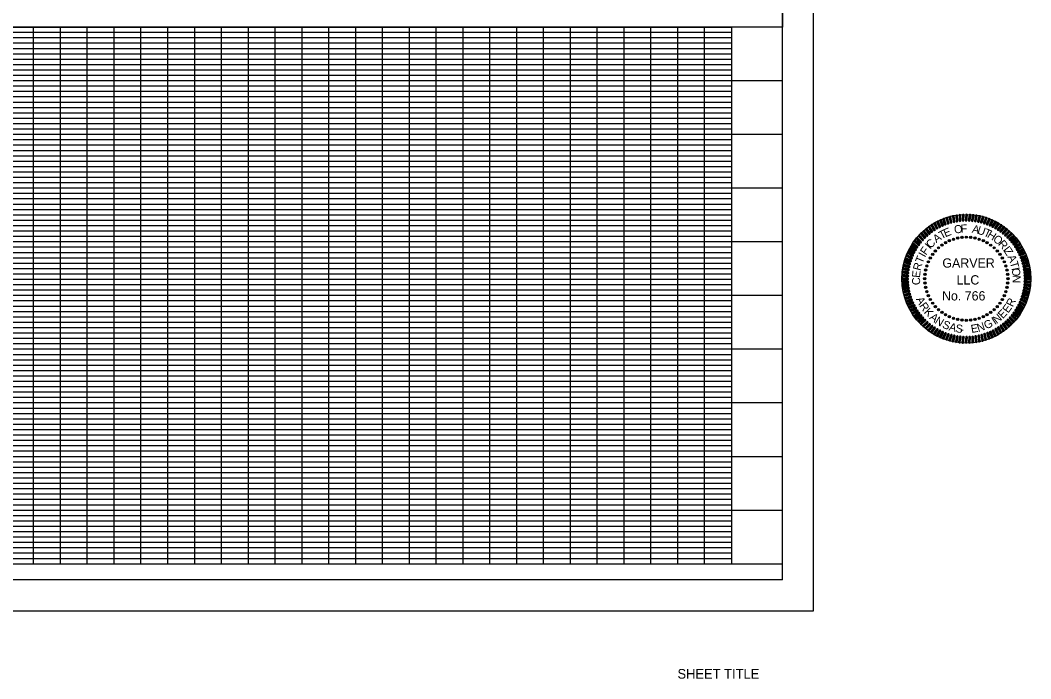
# Model space of a CAD drawing. Extents: x 0 to 762217, y -63 to 1662473.
# Drawn here: x 961 to 1902, y -63 to 550 of the extents above; entities that cross this region are included whole.
import ezdxf

# ---------------------------------------------------------------- set-up
doc = ezdxf.new("R2010")
doc.units = 0
for name, color, linetype in [('G-ANNO-TEXT', 7, 'Continuous'), ('G-Border-Paper', 7, 'Continuous'), ('G-Border-Sheet', 7, 'Continuous'), ('G-Grid-Border', 7, 'Continuous'), ('G-Grid-Major', 7, 'Continuous'), ('G-Grid-Minor', 7, 'Continuous'), ('G-No Plot-Border', 7, 'Continuous'), ('G-No Plot-Border-2', 7, 'Continuous'), ('G-No Plot-Stamp', 7, 'Continuous')]:
    doc.layers.add(name, color=color, linetype=linetype)

# ---------------------------------------------------------------- blocks, each defined once
blk = doc.blocks.new('SEALDO')
at = {"layer": 'G-ANNO-TEXT'}
for radius in [0.0396, 0.0305, 0.0213, 0.0122, 0.00305]:
    blk.add_circle((1.403, -0.456), radius, dxfattribs=at)
blk = doc.blocks.new('SEALRI')
at = {"layer": 'G-ANNO-TEXT'}
for p, q in [((-0.023, 2.258), (-0.038, 2.081)), ((-0.008, 2.281), (-0.028, 2.056)), ((0.004, 2.286), (-0.016, 2.049)), ((0.016, 2.285), (-0.004, 2.048)), ((0.028, 2.278), (0.008, 2.052)), ((0.023, 2.076), (0.038, 2.253))]:
    blk.add_line(p, q, dxfattribs=at)
for centre, start, end in [((0.008, 2.256), 355, 175), ((-0.008, 2.078), 175, 355)]:
    blk.add_arc(centre, 0.0305, start, end, dxfattribs=at)

msp = doc.modelspace()

# ---------------------------------------------------------------- linework, layer by layer
at = {"layer": 'G-Border-Paper'}
msp.add_lwpolyline([(1700.05, 1100), (0.05, 1100), (0.05, 0), (1700.05, 0)], close=True, dxfattribs=at)
at = {"layer": 'G-Border-Sheet'}
for q in [(1671.21, 1071.16), (75.85, 28.84)]:
    msp.add_line((1671.21, 28.84), q, dxfattribs=at)
at = {"layer": 'G-Grid-Border'}
for p, q in [((1671.21, 543.54), (75.85, 543.54)), ((1671.21, 43.54), (75.85, 43.54))]:
    msp.add_line(p, q, dxfattribs=at)
msp.add_lwpolyline([(123.53, 543.54), (1623.53, 543.54), (1623.53, 43.54), (123.53, 43.54)], close=True, dxfattribs=at)
at = {"layer": 'G-Grid-Major'}
for p, q in [((973.53, 43.54), (973.53, 543.54)), ((1023.53, 43.54), (1023.53, 543.54)), ((1073.53, 43.54), (1073.53, 543.54)), ((1123.53, 43.54), (1123.53, 543.54)), ((1173.53, 43.54), (1173.53, 543.54)), ((1223.53, 43.54), (1223.53, 543.54)), ((1273.53, 43.54), (1273.53, 543.54)), ((1323.53, 43.54), (1323.53, 543.54)), ((1373.53, 43.54), (1373.53, 543.54)), ((1423.53, 43.54), (1423.53, 543.54)), ((1473.53, 43.54), (1473.53, 543.54)), ((1523.53, 43.54), (1523.53, 543.54)), ((1573.53, 43.54), (1573.53, 543.54)), ((1671.21, 493.54), (75.85, 493.54)), ((1671.21, 443.54), (75.85, 443.54)), ((1671.21, 393.54), (75.85, 393.54)), ((1671.21, 343.54), (75.85, 343.54)), ((1671.21, 293.54), (75.85, 293.54)), ((1671.21, 243.54), (75.85, 243.54)), ((1671.21, 193.54), (75.85, 193.54)), ((1671.21, 143.54), (75.85, 143.54)), ((1671.21, 93.54), (75.85, 93.54))]:
    msp.add_line(p, q, dxfattribs=at)
msp.add_lwpolyline([(123.53, 543.54), (1623.53, 543.54), (1623.53, 43.54), (123.53, 43.54)], close=True, dxfattribs=at)
at = {"layer": 'G-Grid-Minor'}
for p, q in [((1623.53, 538.54), (123.53, 538.54)), ((998.53, 43.54), (998.53, 543.54)), ((1048.53, 43.54), (1048.53, 543.54)), ((1098.53, 43.54), (1098.53, 543.54)), ((1148.53, 43.54), (1148.53, 543.54)), ((1198.53, 43.54), (1198.53, 543.54)), ((1248.53, 43.54), (1248.53, 543.54)), ((1298.53, 43.54), (1298.53, 543.54)), ((1348.53, 43.54), (1348.53, 543.54)), ((1398.53, 43.54), (1398.53, 543.54)), ((1448.53, 43.54), (1448.53, 543.54)), ((1498.53, 43.54), (1498.53, 543.54)), ((1548.53, 43.54), (1548.53, 543.54)), ((1598.53, 43.54), (1598.53, 543.54)), ((1623.53, 533.54), (123.53, 533.54)), ((1623.53, 528.54), (123.53, 528.54)), ((1623.53, 523.54), (123.53, 523.54)), ((1623.53, 518.54), (123.53, 518.54)), ((1623.53, 513.54), (123.53, 513.54)), ((1623.53, 508.54), (123.53, 508.54)), ((1623.53, 503.54), (123.53, 503.54)), ((1623.53, 498.54), (123.53, 498.54)), ((1623.53, 488.54), (123.53, 488.54)), ((1623.53, 483.54), (123.53, 483.54)), ((1623.53, 478.54), (123.53, 478.54)), ((1623.53, 473.54), (123.53, 473.54)), ((1623.53, 468.54), (123.53, 468.54)), ((1623.53, 463.54), (123.53, 463.54)), ((1623.53, 458.54), (123.53, 458.54)), ((1623.53, 453.54), (123.53, 453.54)), ((1623.53, 448.54), (123.53, 448.54)), ((1623.53, 438.54), (123.53, 438.54)), ((1623.53, 433.54), (123.53, 433.54)), ((1623.53, 428.54), (123.53, 428.54)), ((1623.53, 423.54), (123.53, 423.54)), ((1623.53, 418.54), (123.53, 418.54)), ((1623.53, 413.54), (123.53, 413.54)), ((1623.53, 408.54), (123.53, 408.54)), ((1623.53, 403.54), (123.53, 403.54)), ((1623.53, 398.54), (123.53, 398.54)), ((1623.53, 388.54), (123.53, 388.54)), ((1623.53, 383.54), (123.53, 383.54)), ((1623.53, 378.54), (123.53, 378.54)), ((1623.53, 373.54), (123.53, 373.54)), ((1623.53, 368.54), (123.53, 368.54)), ((1623.53, 363.54), (123.53, 363.54)), ((1623.53, 358.54), (123.53, 358.54)), ((1623.53, 353.54), (123.53, 353.54)), ((1623.53, 348.54), (123.53, 348.54)), ((1623.53, 338.54), (123.53, 338.54)), ((1623.53, 333.54), (123.53, 333.54)), ((1623.53, 328.54), (123.53, 328.54)), ((1623.53, 323.54), (123.53, 323.54)), ((1623.53, 318.54), (123.53, 318.54)), ((1623.53, 313.54), (123.53, 313.54)), ((1623.53, 308.54), (123.53, 308.54)), ((1623.53, 303.54), (123.53, 303.54)), ((1623.53, 298.54), (123.53, 298.54)), ((1623.53, 288.54), (123.53, 288.54)), ((1623.53, 283.54), (123.53, 283.54)), ((1623.53, 278.54), (123.53, 278.54)), ((1623.53, 273.54), (123.53, 273.54)), ((1623.53, 268.54), (123.53, 268.54)), ((1623.53, 263.54), (123.53, 263.54)), ((1623.53, 258.54), (123.53, 258.54)), ((1623.53, 253.54), (123.53, 253.54)), ((1623.53, 248.54), (123.53, 248.54)), ((1623.53, 238.54), (123.53, 238.54)), ((1623.53, 233.54), (123.53, 233.54)), ((1623.53, 228.54), (123.53, 228.54)), ((1623.53, 223.54), (123.53, 223.54)), ((1623.53, 218.54), (123.53, 218.54)), ((1623.53, 213.54), (123.53, 213.54)), ((1623.53, 208.54), (123.53, 208.54)), ((1623.53, 203.54), (123.53, 203.54)), ((1623.53, 198.54), (123.53, 198.54)), ((1623.53, 188.54), (123.53, 188.54)), ((1623.53, 183.54), (123.53, 183.54)), ((1623.53, 178.54), (123.53, 178.54)), ((1623.53, 173.54), (123.53, 173.54)), ((1623.53, 168.54), (123.53, 168.54)), ((1623.53, 163.54), (123.53, 163.54)), ((1623.53, 158.54), (123.53, 158.54)), ((1623.53, 153.54), (123.53, 153.54)), ((1623.53, 148.54), (123.53, 148.54)), ((1623.53, 138.54), (123.53, 138.54)), ((1623.53, 133.54), (123.53, 133.54)), ((1623.53, 128.54), (123.53, 128.54)), ((1623.53, 123.54), (123.53, 123.54)), ((1623.53, 118.54), (123.53, 118.54)), ((1623.53, 113.54), (123.53, 113.54)), ((1623.53, 108.54), (123.53, 108.54)), ((1623.53, 103.54), (123.53, 103.54)), ((1623.53, 98.54), (123.53, 98.54)), ((1623.53, 88.54), (123.53, 88.54)), ((1623.53, 83.54), (123.53, 83.54)), ((1623.53, 78.54), (123.53, 78.54)), ((1623.53, 73.54), (123.53, 73.54)), ((1623.53, 68.54), (123.53, 68.54)), ((1623.53, 63.54), (123.53, 63.54)), ((1623.53, 58.54), (123.53, 58.54)), ((1623.53, 53.54), (123.53, 53.54)), ((1623.53, 48.54), (123.53, 48.54))]:
    msp.add_line(p, q, dxfattribs=at)
at = {"layer": 'G-No Plot-Border'}
msp.add_lwpolyline([(75.85, 543.54), (75.85, 1071.16), (1273.86, 1071.16), (1273.86, 1021.61), (1472.11, 1021.61), (1472.11, 1006.11), (1543.71, 1006.11), (1543.71, 858.61), (1671.21, 858.61), (1671.21, 543.54)], close=True, dxfattribs=at)
at = {"layer": 'G-No Plot-Border-2'}
msp.add_lwpolyline([(75.85, 1071.16), (1147.43, 1071.16), (1147.43, 923.66), (1273.86, 923.66), (1273.86, 1021.61), (1472.11, 1021.61), (1472.11, 1006.11), (1671.21, 1006.11), (1671.21, 543.54), (75.85, 543.54)], close=True, dxfattribs=at)
at = {"layer": 'G-No Plot-Stamp'}
msp.add_circle((1842.27, 309.25), 60, dxfattribs=at)
msp.add_circle((1842.27, 309.25), 60, dxfattribs=at)

# ---------------------------------------------------------------- block references
at = {"layer": 'G-ANNO-TEXT'}
for name, xscale, yscale, rotation in [('SEALRI', 26.24620298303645, 26.24620298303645, 15.000000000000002), ('SEALRI', 26.246202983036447, 26.246202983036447, 12.000000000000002), ('SEALRI', 26.246202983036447, 26.246202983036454, 9), ('SEALRI', 26.246202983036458, 26.246202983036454, 6), ('SEALRI', 26.246202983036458, 26.246202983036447, 3.0000000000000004), ('SEALRI', 26.246202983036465, 26.246202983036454, -2.9999999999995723), ('SEALRI', 26.24620298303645, 26.246202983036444, -5.9999999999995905), ('SEALRI', 26.246202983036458, 26.24620298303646, -8.999999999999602), ('SEALRI', 26.246202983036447, 26.246202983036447, -11.999999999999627), ('SEALRI', 26.24620298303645, 26.246202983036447, -14.999999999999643), ('SEALRI', 26.24620298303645, 26.246202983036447, 36), ('SEALRI', 26.24620298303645, 26.246202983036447, 33), ('SEALRI', 26.24620298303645, 26.246202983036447, 30.00000000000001), ('SEALRI', 26.246202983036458, 26.246202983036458, 26.999999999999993), ('SEALRI', 26.246202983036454, 26.24620298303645, 23.99999999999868), ('SEALRI', 26.246202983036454, 26.24620298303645, 20.99999999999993), ('SEALRI', 26.246202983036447, 26.24620298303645, 18), ('SEALRI', 26.24620298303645, 26.24620298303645, -17.999999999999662), ('SEALRI', 26.24620298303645, 26.246202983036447, -20.999999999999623), ('SEALRI', 26.246202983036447, 26.24620298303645, -23.99999999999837), ('SEALRI', 26.246202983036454, 26.24620298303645, -26.999999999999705), ('SEALRI', 26.24620298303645, 26.246202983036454, -29.99999999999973), ('SEALRI', 26.24620298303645, 26.246202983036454, -32.999999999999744), ('SEALRI', 26.24620298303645, 26.246202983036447, -35.999999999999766), ('SEALRI', 26.246202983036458, 26.246202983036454, 47.99999999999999), ('SEALRI', 26.24620298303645, 26.246202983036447, 44.999999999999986), ('SEALRI', 26.246202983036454, 26.24620298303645, 41.999999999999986), ('SEALRI', 26.246202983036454, 26.24620298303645, 38.999999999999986), ('SEALDO', 26.246202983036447, 26.24620298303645, 119.99999999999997), ('SEALDO', 26.24620298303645, 26.246202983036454, 113.99999999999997), ('SEALDO', 26.24620298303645, 26.246202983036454, 107.99999999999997), ('SEALDO', 26.24620298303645, 26.246202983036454, 101.99999999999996), ('SEALRI', 26.24620298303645, 26.24620298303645, -38.99999999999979), ('SEALRI', 26.24620298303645, 26.24620298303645, -41.99999999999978), ('SEALRI', 26.246202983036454, 26.24620298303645, -44.99999999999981), ('SEALRI', 26.246202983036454, 26.24620298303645, -47.99999999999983), ('SEALRI', 26.246202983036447, 26.24620298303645, 59.999999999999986), ('SEALRI', 26.246202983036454, 26.246202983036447, 56.99999999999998), ('SEALRI', 26.24620298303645, 26.246202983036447, 54), ('SEALRI', 26.246202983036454, 26.24620298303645, 50.99999999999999), ('SEALDO', 26.246202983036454, 26.24620298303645, 150), ('SEALDO', 26.246202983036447, 26.24620298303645, 144), ('SEALDO', 26.24620298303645, 26.246202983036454, 138), ('SEALDO', 26.246202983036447, 26.246202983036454, 131.99999999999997), ('SEALDO', 26.246202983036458, 26.246202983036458, 125.99999999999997), ('SEALDO', 26.246202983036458, 26.246202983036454, 95.99999999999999), ('SEALDO', 26.246202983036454, 26.24620298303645, 90), ('SEALDO', 26.246202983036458, 26.246202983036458, 83.99999999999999), ('SEALDO', 26.246202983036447, 26.24620298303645, 77.99999999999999), ('SEALDO', 26.246202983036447, 26.24620298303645, 72), ('SEALDO', 26.246202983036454, 26.24620298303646, 66.00000000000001), ('SEALRI', 26.246202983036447, 26.24620298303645, -50.99999999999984), ('SEALRI', 26.24620298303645, 26.24620298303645, -53.99999999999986), ('SEALRI', 26.246202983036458, 26.246202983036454, -56.999999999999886), ('SEALRI', 26.24620298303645, 26.24620298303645, -59.99999999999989), ('SEALRI', 26.246202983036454, 26.24620298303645, 68.99999999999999), ('SEALRI', 26.246202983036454, 26.24620298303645, 65.99999999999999), ('SEALRI', 26.246202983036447, 26.246202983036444, 63), ('SEALDO', 26.24620298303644, 26.24620298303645, 168.00000000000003), ('SEALDO', 26.246202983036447, 26.246202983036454, 162.00000000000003), ('SEALDO', 26.24620298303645, 26.246202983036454, 156.00000000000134), ('SEALDO', 26.246202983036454, 26.24620298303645, 60.00000000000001), ('SEALDO', 26.24620298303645, 26.246202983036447, 54), ('SEALDO', 26.246202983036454, 26.24620298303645, 48.000000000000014), ('SEALRI', 26.246202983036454, 26.246202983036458, -62.99999999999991), ('SEALRI', 26.246202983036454, 26.24620298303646, -65.99999999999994), ('SEALRI', 26.246202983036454, 26.24620298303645, -68.99999999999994), ('SEALRI', 26.246202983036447, 26.246202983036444, 78.00000000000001), ('SEALRI', 26.24620298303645, 26.246202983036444, 75.00000000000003), ('SEALRI', 26.246202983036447, 26.24620298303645, 72), ('SEALDO', 26.246202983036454, 26.24620298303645, -179.99999999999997), ('SEALDO', 26.246202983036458, 26.246202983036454, 174.00000000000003), ('SEALDO', 26.246202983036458, 26.246202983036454, 42.00000000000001), ('SEALDO', 26.24620298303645, 26.246202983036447, 36), ('SEALRI', 26.24620298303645, 26.24620298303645, -71.99999999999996), ('SEALRI', 26.246202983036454, 26.24620298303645, -74.99999999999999), ('SEALRI', 26.246202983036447, 26.246202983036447, -78), ('SEALRI', 26.24620298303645, 26.246202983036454, 87.00000000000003), ('SEALRI', 26.246202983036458, 26.246202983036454, 84.00000000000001), ('SEALRI', 26.246202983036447, 26.246202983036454, 81), ('SEALDO', 26.246202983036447, 26.24620298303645, -167.99999999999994), ('SEALDO', 26.24620298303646, 26.246202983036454, -173.99999999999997), ('SEALDO', 26.246202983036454, 26.24620298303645, 29.999999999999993), ('SEALDO', 26.246202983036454, 26.24620298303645, 23.99999999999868), ('SEALRI', 26.246202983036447, 26.246202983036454, -81.00000000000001), ('SEALRI', 26.246202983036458, 26.246202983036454, -84.00000000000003), ('SEALRI', 26.24620298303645, 26.24620298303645, -87.00000000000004), ('SEALRI', 26.246202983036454, 26.24620298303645, 90.00000000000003), ('SEALRI', 26.246202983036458, 26.246202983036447, 93), ('SEALRI', 26.246202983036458, 26.246202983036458, 96.00000000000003), ('SEALRI', 26.246202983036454, 26.246202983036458, 99.00000000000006), ('SEALDO', 26.24620298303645, 26.246202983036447, -161.99999999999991), ('SEALDO', 26.24620298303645, 26.24620298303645, -156.00000000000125), ('SEALDO', 26.24620298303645, 26.246202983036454, -149.99999999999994), ('SEALDO', 26.246202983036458, 26.246202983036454, 6), ('SEALDO', 26.246202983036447, 26.246202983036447, 12.000000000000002), ('SEALDO', 26.246202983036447, 26.24620298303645, 18), ('SEALRI', 26.246202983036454, 26.246202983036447, -99.00000000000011), ('SEALRI', 26.24620298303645, 26.246202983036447, -96.0000000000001), ('SEALRI', 26.246202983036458, 26.246202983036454, -93.00000000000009), ('SEALRI', 26.246202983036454, 26.24620298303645, -90.00000000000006), ('SEALRI', 26.246202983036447, 26.246202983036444, 102.00000000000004), ('SEALRI', 26.246202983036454, 26.24620298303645, 105.00000000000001), ('SEALRI', 26.24620298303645, 26.24620298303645, 108.00000000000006), ('SEALDO', 26.246202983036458, 26.246202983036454, -143.99999999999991), ('SEALDO', 26.246202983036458, 26.246202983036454, -137.9999999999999), ('SEALDO', 26.24620298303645, 26.24620298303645, -6.000000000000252), ('SEALRI', 26.246202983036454, 26.246202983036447, -108.00000000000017), ('SEALRI', 26.246202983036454, 26.24620298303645, -105.00000000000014), ('SEALRI', 26.246202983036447, 26.246202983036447, -102.00000000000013), ('SEALRI', 26.24620298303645, 26.246202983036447, 111.00000000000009), ('SEALRI', 26.246202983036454, 26.246202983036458, 114.00000000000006), ('SEALRI', 26.24620298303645, 26.246202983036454, 117.00000000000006), ('SEALRI', 26.246202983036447, 26.24620298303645, 120.00000000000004), ('SEALDO', 26.24620298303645, 26.246202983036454, -131.99999999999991), ('SEALDO', 26.24620298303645, 26.246202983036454, -125.9999999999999), ('SEALDO', 26.24620298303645, 26.24620298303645, -119.99999999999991), ('SEALDO', 26.246202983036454, 26.246202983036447, -23.999999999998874), ('SEALDO', 26.246202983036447, 26.24620298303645, -18.000000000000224), ('SEALDO', 26.246202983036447, 26.246202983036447, -12.000000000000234), ('SEALRI', 26.24620298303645, 26.24620298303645, -120.00000000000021), ('SEALRI', 26.24620298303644, 26.24620298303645, -117.00000000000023), ('SEALRI', 26.246202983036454, 26.246202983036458, -114.0000000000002), ('SEALRI', 26.24620298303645, 26.246202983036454, -111.00000000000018), ('SEALRI', 26.24620298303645, 26.246202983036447, 123.00000000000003), ('SEALRI', 26.24620298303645, 26.246202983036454, 126.00000000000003), ('SEALRI', 26.246202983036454, 26.24620298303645, 129.00000000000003), ('SEALRI', 26.24620298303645, 26.24620298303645, 132), ('SEALDO', 26.246202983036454, 26.246202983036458, -113.99999999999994), ('SEALDO', 26.24620298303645, 26.24620298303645, -107.99999999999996), ('SEALDO', 26.246202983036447, 26.246202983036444, -101.99999999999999), ('SEALDO', 26.246202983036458, 26.246202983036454, -96), ('SEALDO', 26.246202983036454, 26.24620298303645, -90.00000000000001), ('SEALDO', 26.24620298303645, 26.24620298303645, -54.000000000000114), ('SEALDO', 26.246202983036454, 26.246202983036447, -48.00000000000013), ('SEALDO', 26.24620298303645, 26.246202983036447, -42.00000000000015), ('SEALDO', 26.24620298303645, 26.24620298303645, -36.00000000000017), ('SEALDO', 26.24620298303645, 26.246202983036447, -30.00000000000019), ('SEALRI', 26.246202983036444, 26.24620298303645, -132.00000000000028), ('SEALRI', 26.246202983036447, 26.24620298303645, -129.00000000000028), ('SEALRI', 26.24620298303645, 26.24620298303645, -126.00000000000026), ('SEALRI', 26.246202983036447, 26.246202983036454, -123.00000000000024), ('SEALRI', 26.24620298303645, 26.246202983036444, 135), ('SEALRI', 26.24620298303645, 26.246202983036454, 138), ('SEALRI', 26.246202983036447, 26.24620298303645, 140.99999999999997), ('SEALRI', 26.246202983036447, 26.24620298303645, 144), ('SEALRI', 26.24620298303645, 26.246202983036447, 146.99999999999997), ('SEALDO', 26.246202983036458, 26.246202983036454, -84.00000000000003), ('SEALDO', 26.24620298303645, 26.246202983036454, -78.00000000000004), ('SEALDO', 26.24620298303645, 26.246202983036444, -72.00000000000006), ('SEALDO', 26.246202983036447, 26.246202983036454, -66.00000000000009), ('SEALDO', 26.24620298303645, 26.246202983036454, -60.0000000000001), ('SEALRI', 26.24620298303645, 26.246202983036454, -147.00000000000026), ('SEALRI', 26.246202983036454, 26.246202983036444, -144.00000000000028), ('SEALRI', 26.24620298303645, 26.24620298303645, -141.0000000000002), ('SEALRI', 26.24620298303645, 26.246202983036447, -138.00000000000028), ('SEALRI', 26.246202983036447, 26.24620298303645, -135.00000000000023), ('SEALRI', 26.24620298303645, 26.246202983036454, 149.99999999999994), ('SEALRI', 26.246202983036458, 26.246202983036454, 152.99999999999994), ('SEALRI', 26.24620298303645, 26.246202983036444, 156.00000000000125), ('SEALRI', 26.24620298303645, 26.24620298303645, 159), ('SEALRI', 26.246202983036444, 26.246202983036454, 161.99999999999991), ('SEALRI', 26.24620298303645, 26.246202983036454, 164.99999999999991), ('SEALRI', 26.246202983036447, 26.246202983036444, 167.99999999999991), ('SEALRI', 26.246202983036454, 26.246202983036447, 170.9999999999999), ('SEALRI', 26.24620298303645, 26.24620298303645, 173.9999999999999), ('SEALRI', 26.246202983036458, 26.246202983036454, 176.9999999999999), ('SEALRI', 26.246202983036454, 26.24620298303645, 179.99999999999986), ('SEALRI', 26.246202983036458, 26.246202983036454, -177.00000000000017), ('SEALRI', 26.24620298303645, 26.246202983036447, -174.00000000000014), ('SEALRI', 26.246202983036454, 26.24620298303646, -171.00000000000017), ('SEALRI', 26.246202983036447, 26.24620298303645, -168.0000000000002), ('SEALRI', 26.24620298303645, 26.246202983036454, -165.0000000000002), ('SEALRI', 26.24620298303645, 26.24620298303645, -162.0000000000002), ('SEALRI', 26.24620298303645, 26.246202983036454, -159.00000000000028), ('SEALRI', 26.246202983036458, 26.246202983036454, -156.00000000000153), ('SEALRI', 26.24620298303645, 26.246202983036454, -153.00000000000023), ('SEALRI', 26.246202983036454, 26.246202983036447, -150.00000000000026)]:
    msp.add_blockref(name, (1842.28, 309.25), dxfattribs=dict(at, xscale=xscale, yscale=yscale, rotation=rotation))
at = {"layer": 'G-ANNO-TEXT', "xscale": 26.246202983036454, "yscale": 26.24620298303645}
for name in ['SEALRI', 'SEALDO']:
    msp.add_blockref(name, (1842.28, 309.25), dxfattribs=at)

# ---------------------------------------------------------------- texts
at = {"layer": 'G-ANNO-TEXT'}
for s, rotation, p in [('O', 8.2771, (1831.41, 351.23)), ('F', 1.61044, (1837.09, 352.2)), ('A', 348.2771, (1847.12, 352.27)), ('U', 341.27715, (1851.81, 351.52)), ('A', 34.94377, (1814.33, 342.28)), ('T', 28.2771, (1819.1, 345.73)), ('E', 21.61044, (1822.72, 347.85)), ('T', 334.94377, (1857.7, 349.62)), ('H', 328.2771, (1861.08, 348.28)), ('O', 319.7874, (1866.5, 345.2)), ('F', 54.94377, (1804.72, 330.73)), ('I', 49.74076, (1808.63, 336.22)), ('C', 44.38813, (1809.01, 336.99)), ('R', 311.99331, (1871.42, 341.28)), ('I', 307.00814, (1876, 336.13)), ('T', 67.43139, (1801.31, 322.89)), ('I', 61.61044, (1803.83, 328.71)), ('Z', 301.61044, (1876.88, 335.23)), ('A', 292.97516, (1880.42, 329.78)), ('R', 74.94377, (1799.56, 316.29)), ('T', 286.3085, (1882.77, 324.35)), ('E', 83.89849, (1799.02, 309.87)), ('I', 281.61044, (1884.27, 319.08)), ('O', 276.48226, (1884.56, 318.81)), ('N', 268.2771, (1885.49, 312.48)), ('C', 91.88416, (1799.35, 303.47)), ('A', 296.57465, (1795.19, 290.25)), ('R', 304.61826, (1798.15, 284.08)), ('E', 54.73091, (1881.31, 276.72)), ('R', 63.09594, (1885.48, 282.47)), ('K', 313.3805, (1802.36, 277.8)), ('A', 321.25836, (1807.43, 272.32)), ('N', 329.10994, (1812.36, 268.17)), ('I', 32.97899, (1868.81, 266.12)), ('N', 38.98211, (1870.55, 267.01)), ('E', 46.68075, (1876.34, 271.59)), ('S', 337.62936, (1819.28, 263.96)), ('A', 345.40726, (1825.6, 261.3)), ('S', 352.80457, (1831.96, 259.52)), ('E', 10.06947, (1847.18, 258.71)), ('N', 17.86862, (1853.46, 259.65)), ('G', 26.41319, (1860.85, 261.94)), ('-', 0.83848, (1836.49, 258.54))]:
    msp.add_text(s, height=7.5, rotation=rotation, dxfattribs=at).set_placement(p)
for s, height, p in [('GARVER', 8.64, (1819.98, 319.61)), ('LLC', 8.64, (1833.19, 303.9)), ('No. 766', 8.64, (1819.61, 289.03)), ('SHEET TITLE', 9, (1573.24, -63.18))]:
    msp.add_text(s, height=height, dxfattribs=at).set_placement(p)

doc.saveas('drawing.dxf')
